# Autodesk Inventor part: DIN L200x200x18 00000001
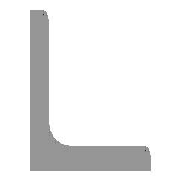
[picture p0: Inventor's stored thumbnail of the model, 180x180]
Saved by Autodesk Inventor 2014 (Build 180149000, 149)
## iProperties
_CCFamilyMember: 400
_CCFamilyDisplayName: DIN EN 10056-1 (Hot-rolled structural steel section-Equal angles) - Hot-rolled structural steel section-Equal angles
_FrameMemberDoc: Frame Member File
_Version: 15.0.0
Created: 2009-11
Part Number: DIN L200x200x18 00000001
Material: Steel, Mild
Description: Hot-rolled structural steel section-Equal angles
Document SubType Name: Modeling
Standard: DIN
Designer: pokornp
Standard Revision: 1998
Standards Organization: DIN
Language: en-US
Size Designation: L200x200x18
Categories: <MemberInstance><Categories><Category DisplayName="Structural Shapes" InternalName="089c4875-fa83-4c05-b084-43b9cc11f5ed" Mnemonic="GRDR"><CategoryParameter Dis
Stock Number: L200x200x18
Density: 7.86 g/cm^3
Mass: 106464 g
Surface Area: 15515.4 cm^2
Volume: 13545.1 cm^3
Appearance: Steel
IsCustomPart: 1
G_L: 1960.000 mm
G_W: 200.000 mm
G_H: 200.000 mm
Author: pokornp
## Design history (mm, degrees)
node "Start plane"
node "End plane"
sketch "Sketch"
  geometry: L1 (-37.533, -19.533)-(-37.533, 135.467); L2 (-55.533, 144.467)-(-46.533, 144.467); L3 (-55.533, -55.533)-(-55.533, 144.467); L4 (-55.533, -55.533)-(144.467, -55.533); L5 (144.467, -46.533)-(144.467, -55.533); L6 (-19.533, -37.533)-(135.467, -37.533); L7 (0, 186.703)-(0, -95.906) reference; L8 (-95.906, 0)-(186.703, 0) reference; A1 r 18 centre (-19.533, -19.533) between (-37.533, -19.533) and (-19.533, -37.533); A2 r 9 centre (-46.533, 135.467) between (-37.533, 135.467) and (-46.533, 144.467); A3 r 9 centre (135.467, -46.533) between (144.467, -46.533) and (135.467, -37.533); 3 further points
  constraints: 12 end point, 6 point on circle, 6 point on line, 6 tangent, 3 centre point, 3 horizontal, 3 vertical, 1 equal radius
  dimensions: "d4" = 200 distance of L3.start L4.end (= b); "d6" = 200 distance of L3.start L2.start (= b); "d8" = 18 distance of point (144.467, -37.533) L4.end (= ParT); "d10" = 18 distance of L2.start point (-37.533, 144.467) (= ParT); "d17" = 18 radius of A1 (= R); "d18" = 9 radius of A2 (= R1); "d19" = 55.53331 distance between parallel lines of L8 L4 (= ex); "d20" = 55.53331 distance between parallel lines of L3 L7 (= d19)
extrude "Body" new body sketch "Sketch" stored distance "d11" = 1960 (= G_L); taper "d12" = 0 deg
node "Driven Length"
  sketch "Sketch3"
    geometry: L1 (0, 0)-(10, 0) reference
    constraints: 2 end point, 1 horizontal
  workplane "Work Plane10"
  sketch "Sketch4"
    geometry: L1 (-2, 0)-(12, 0) reference; L2 (-2, 1960)-(12, 1960) reference
    dimensions: "d24" = 1960 distance between parallel lines of L1 L2 (derived)
body "Solid1"
other parameters: "b" = 200 [user parameter; used in 3 equation terms], "ParT" = 18 [user parameter; used in 3 equation terms], "R" = 18 [user parameter; used in 1 equation term], "R1" = 9 [user parameter; used in 1 equation term], "G_L" = 1960 (= d24) [user parameter; used in 1 equation term], "d7" = 4 (derived), "d9" = 4 (derived), "ex" = 55.53331 (computed from b, ParT) [user parameter; used in 1 equation term], "G_OFFSET_START" = 0 [user parameter; used in 1 equation term], "G_OFFSET_END" = 0 [user parameter; used in 1 equation term], "d21" = 0 (computed from G_OFFSET_START), "d23" = 90 deg
